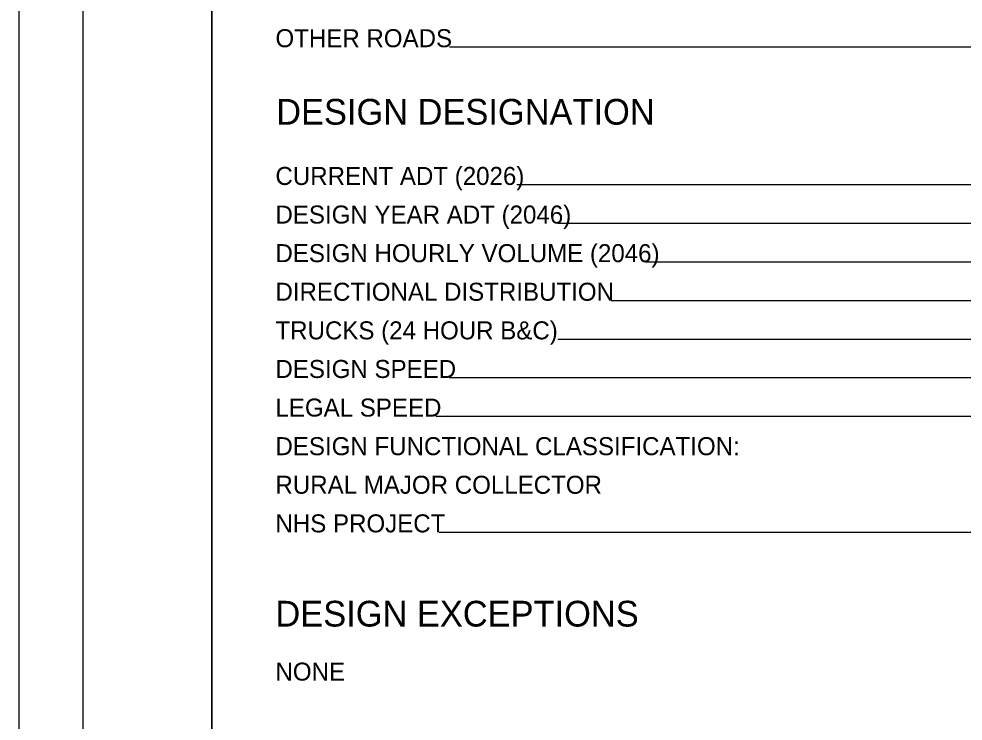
# Model space of a CAD drawing. Extents: x 0 to 40.9, y 0 to 22.
# Drawn here: x 0 to 7.34, y 5.64 to 11.1 of the extents above; entities that cross this region are included whole.
import ezdxf

# ---------------------------------------------------------------- set-up
doc = ezdxf.new("R2010")
doc.units = 0
for name, color, linetype in [('SH_Border', 7, 'Continuous'), ('SH_Cut_Line', 7, 'Continuous'), ('SH_Data', 7, 'Continuous'), ('SH_Text', 7, 'Continuous')]:
    doc.layers.add(name, color=color, linetype=linetype)

msp = doc.modelspace()

# ---------------------------------------------------------------- linework, layer by layer
at = {"layer": 'SH_Cut_Line'}
for p, q in [((7.7, 10.8767), (3.3471, 10.8767)), ((7.6424, 9.8062), (3.871, 9.8062)), ((7.6368, 9.5062), (4.1885, 9.5062)), ((7.6368, 9.2062), (4.8723, 9.2062)), ((7.6368, 8.9062), (4.6037, 8.9062)), ((7.6368, 8.6062), (4.1885, 8.6062)), ((7.6368, 8.3062), (3.346, 8.3062)), ((7.6368, 8.0062), (3.2422, 8.0062)), ((7.6368, 7.1062), (3.2669, 7.1062))]:
    msp.add_line(p, q, dxfattribs=at)
at = {"layer": 'SH_Data'}
msp.add_lwpolyline([(0, 0), (34, 0), (34, 22), (0, 22)], close=True, dxfattribs=at)
at = {"layer": 'SH_Text'}
for points in [[(0.5, 21.5), (1.5, 21.5), (1.5, 0.5), (0.5, 0.5)], [(1.5, 21.5), (33.5, 21.5), (33.5, 0.5), (1.5, 0.5)]]:
    msp.add_lwpolyline(points, close=True, dxfattribs=at)

# ---------------------------------------------------------------- texts
at = {"layer": 'SH_Border'}
for s, height, p in [('OTHER ROADS', 0.14, (1.9944, 10.8767)), ('CURRENT ADT (2026)', 0.14, (1.9944, 9.8062)), ('DESIGN YEAR ADT (2046)', 0.14, (1.9944, 9.5062)), ('DESIGN HOURLY VOLUME (2046)', 0.14, (1.9944, 9.2062)), ('DIRECTIONAL DISTRIBUTION', 0.14, (1.9944, 8.9062)), ('TRUCKS (24 HOUR B&C)', 0.14, (1.9944, 8.6062)), ('DESIGN SPEED', 0.14, (1.9944, 8.3062)), ('LEGAL SPEED', 0.14, (1.9944, 8.0062)), ('DESIGN FUNCTIONAL CLASSIFICATION:', 0.14, (1.9944, 7.7062)), ('RURAL MAJOR COLLECTOR', 0.14, (1.9944, 7.4062)), ('NHS PROJECT', 0.14, (1.9944, 7.1062)), ('DESIGN EXCEPTIONS', 0.2, (1.9944, 6.3744)), ('NONE', 0.14, (1.9944, 5.9544))]:
    msp.add_text(s, height=height, dxfattribs=at).set_placement(p)
at = {"layer": 'SH_Cut_Line'}
msp.add_text('DESIGN DESIGNATION', height=0.2, dxfattribs=at).set_placement((2, 10.2747))

doc.saveas('drawing.dxf')
